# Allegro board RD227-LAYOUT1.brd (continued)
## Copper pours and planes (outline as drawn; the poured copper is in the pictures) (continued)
SHLD_SNS on TOP: 72.97,0.99 72.95,0.99 72.94,1 72.16,1.78 72.15,1.8 72.14,1.82 72.14,5.73 72.15,5.75 72.16,5.76 72.53,6.14 72.54,6.15 72.56,6.15 74.2,6.15 74.2,6.45 73.51,6.45 73.41,6.49 73.36,6.6 73.36,7.61 73.41,7.72 73.51,7.76 77.51,7.76 79.15,9.4 79.15,11.55 79.16,11.59 79.2,11.6 81.1,11.6 81.1,12.4 79.2,12.4 79.16,12.41 79.15,12.45 79.15,13.55 79.16,13.59 79.2,13.6 81.15,13.6 81.15,14.4 79.2,14.4 79.16,14.41 79.15,14.45 79.15,15.6 79.16,15.64 79.2,15.65 84.35,15.65 85.29,16.59 85.29,28.04 82.9,30.43 80.88,30.43 80.77,30.47 80.73,30.58 80.73,32.57 80.77,32.68 80.88,32.72 88.78,32.72 88.88,32.68 88.93,32.57 88.93,27.29 88.92,27.24 88.9,27.19 88.9,25.78 88.85,25.68 86.89,23.72 86.89,17.26 88.91,15.24 88.92,15.22 88.93,15.2 88.93,7.65 88.88,7.54 88.78,7.5 85.45,7.5 78.95,1 78.94,0.99 78.92,0.99
SHLD_SNS on CONDUCTIVE2: 72.21,1.74 72.2,1.75 72.2,1.77 72.2,2.72 72.19,2.75 72.19,4.67 72.2,4.7 72.2,5.78 72.2,5.8 72.21,5.81 74.14,7.74 74.15,7.75 74.17,7.75 77.45,7.75 83.42,13.72 83.44,13.74 83.46,13.74 86.55,13.74 86.58,13.72 86.6,13.69 86.6,8.67 86.59,8.65 86.58,8.63 78.95,1 78.94,0.99 78.92,0.99 73.03,0.99 72.92,1.03
SHLD_SNS on CONDUCTIVE3: 72.21,1.54 72.2,1.55 72.2,1.57 72.2,5.78 72.2,5.8 72.21,5.81 74.24,7.84 74.25,7.85 74.27,7.85 77.55,7.85 83.64,13.94 83.66,13.95 83.67,13.95 86.64,13.95 86.68,13.94 86.69,13.9 86.69,8.76 86.69,8.74 86.68,8.73 78.95,1 78.94,0.99 78.92,0.99 72.83,0.99 72.72,1.03
SIG341 on TOP: 45.7,11.8 45.66,11.81 45.65,11.85 45.65,12.03 45.65,12.05 45.66,12.06 46.6,13 46.6,13.3 46.61,13.34 46.63,13.37 46.83,13.57 46.86,13.59 46.9,13.6 47,13.6 47.1,13.5 47,13.4 46.94,13.4 46.8,13.26 46.8,12.7 46.8,12.65 46.8,12.45 46.8,12.43 46.79,12.41 46.19,11.81 46.17,11.8 46.15,11.8 45.94,11.8 45.92,11.78 45.84,11.75 45.76,11.8
SIG344 on TOP: 54.05,9.7 53.98,9.73 53.95,9.8 53.95,9.95 53.73,10.17 53.71,10.2 53.7,10.24 53.7,10.68 53.7,10.71 53.72,10.74 53.46,11 53.09,11 53.05,11.01 53.02,11.03 51.63,12.42 51.61,12.45 51.6,12.49 51.6,13.05 51.7,13.15 51.8,13.05 51.8,12.55 53.15,11.2 53.5,11.2 53.57,11.17 53.99,10.75 54.05,10.75 54.12,10.72 54.15,10.65 54.15,10.3 54.52,9.93 54.54,9.9 54.55,9.86 54.55,9.8 54.52,9.73 54.45,9.7
SIG345 on TOP: 52.9,9.65 52.83,9.68 52.8,9.75 52.8,10.01 52.81,10.05 52.83,10.08 52.85,10.1 52.85,10.6 51.13,12.32 51.11,12.35 51.1,12.39 51.1,13.05 51.2,13.15 51.3,13.05 51.3,12.45 52.98,10.77 53.19,10.77 53.26,10.74 53.29,10.67 53.29,10.11 53.47,9.93 53.49,9.9 53.5,9.86 53.5,9.75 53.47,9.68 53.4,9.65
SIG347 on TOP: 51.7,9.9 51.63,9.93 51.6,10 51.6,11.1 50.63,12.07 50.6,12.14 50.6,13.05 50.7,13.15 50.8,13.05 50.8,12.35 52.37,10.78 52.39,10.75 52.4,10.71 52.4,10 52.37,9.93 52.3,9.9
SIG369 on TOP: 46.41,10.25 46.34,10.28 46.31,10.35 46.31,11.48 46.32,11.52 46.34,11.55 47.6,12.81 47.6,13.05 47.7,13.15 47.8,13.05 47.8,12.59 47.79,12.55 47.77,12.52 47.48,12.23 47.45,12.21 47.41,12.2 47.27,12.2 46.64,11.56 46.64,10.81 46.82,10.63 46.84,10.6 46.85,10.56 46.85,10.35 46.82,10.28 46.75,10.25
SIG422 on BOTTOM: 29,11 28.96,11.01 28.95,11.05 28.95,13.2 28.96,13.24 29,13.25 29.78,13.25 29.8,13.25 29.81,13.24 30.9,12.15 31.25,12.15 31.9,12.8 31.9,14.6 31.91,14.64 31.95,14.65 32.3,14.65 32.34,14.64 32.35,14.6 32.35,12.55 32.74,12.16 32.75,12.15 32.75,12.13 32.75,11.2 32.74,11.16 32.7,11.15 30.9,11.15 30.76,11.01 30.75,11 30.73,11
SIG426 on BOTTOM: 28.65,22.35 28.61,22.36 28.6,22.4 28.6,24 28.3,24.3 26.8,24.3 26.76,24.31 26.75,24.35 26.75,26.55 26.76,26.59 26.8,26.6 29.3,26.6 29.34,26.59 29.35,26.55 29.35,23.1 29.55,22.9 29.9,22.9 29.94,22.89 29.95,22.85 29.95,22.4 29.94,22.36 29.9,22.35
SIG428 on TOP: 13.35,3.45 13.31,3.46 13.3,3.5 13.3,4.55 13.31,4.59 13.35,4.6 14.05,4.6 14.09,4.59 14.1,4.55 14.1,3.5 14.09,3.46 14.05,3.45
SIG429 on TOP: 12.25,3.85 12.21,3.86 12.2,3.9 12.2,5.2 12.21,5.24 12.25,5.25 12.65,5.25 12.69,5.24 12.7,5.2 12.7,3.9 12.69,3.86 12.65,3.85
SIG449 on BOTTOM: 28.65,20.45 28.61,20.46 28.6,20.5 28.6,21 28.61,21.04 28.65,21.05 29.15,21.05 30.04,21.94 30.05,21.95 30.07,21.95 30.35,21.95 30.65,22.25 30.65,22.85 30.66,22.89 30.7,22.9 31.95,22.9 31.99,22.89 32,22.85 32,22.47 32,22.45 31.99,22.44 31.91,22.36 31.9,22.35 31.88,22.35 31.45,22.35 30.56,21.46 30.55,21.45 30.53,21.45 30.2,21.45 29.9,21.15 29.9,20.5 29.89,20.46 29.85,20.45
SIG450 on BOTTOM: 28.27,19.1 28.25,19.1 28.24,19.11 27.21,20.14 27.2,20.15 27.2,20.17 27.2,23.5 27.05,23.65 26.8,23.65 26.76,23.66 26.75,23.7 26.75,23.95 26.76,23.99 26.8,24 27.55,24 27.59,23.99 27.6,23.95 27.6,20.4 28.45,19.55 31.6,19.55 31.61,19.56 31.75,19.7 31.75,20.2 31.45,20.5 30.65,20.5 30.61,20.51 30.6,20.55 30.6,20.95 30.61,20.99 30.65,21 31.9,21 31.94,20.99 31.95,20.95 31.95,20.7 32.39,20.26 32.4,20.25 32.4,20.23 32.4,19.3 32.39,19.26 32.35,19.25 32.35,19.15 32.34,19.11 32.3,19.1

Small or netless copper shapes (teardrops, artwork), in the pictures only: 41 on TOP, 46 on BOTTOM, 5 on CONDUCTIVE2, 14 on CONDUCTIVE3

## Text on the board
Ref Des/Silkscreen Bottom: UL
Ref Des/Silkscreen Top: 1 | 5 | 10 | 2
SYMBOL-1-BOTTOM: UL
SYMBOL-1-TOP: 1 | 5 | 10 | 2
User.5: Q101 | C121 | C122 | R110 | R117 | Q102 | D101 | IC101 | C118 | C144 | D104 | R103 | TP117 | TP118 | TP124 | TP123 | TP122 | R107 | R101 | D103 | R102 | R113 | R134 | R135 | D106 | C119 | C139 | R139 | R136 | R138 | R140 | C153 | R141 | R137 | C154 | C155 | C150 | C149 | D108 | D109 | TP103 | TP134 | TP104 | TP105 | TP133 | TP132 | TP110 | TP108 | TP111 | CURRENT COMP | VOLTAGE COMP | ADDR SELECT | TP112 | TP131 | R125 | R122 | R121 | R128 | R127 | FL101 | R124 | TP102 | R123 | C141 | D102 | D105 | R115 | D107 | R116 | R114 | TP119 | C151 | R133 | C152 | TP107 | TP106 | TP109 | UL
User.6: C106 | C102 | L101 | TP101 | C116 | CN102 | C103 | R104 | Q103 | C114 | C109 | C104 | TP125 | TP127 | TP126 | IC102 | R126 | Q106 | R112 | C133 | C131 | C143 | R130 | C123 | R131 | R132 | TP116 | C129 | R120 | C135 | R119 | C138 | R106 | C126 | TP115 | C111 | C110 | C105 | C101 | CN101 | C107 | C112 | C115 | C108 | C113 | R108 | R109 | C117 | C120 | Q104 | C145 | R111 | C142 | Q105 | C146 | TP121 | C140 | TP120 | L102 | R129 | C147 | R105 | C148 | C128 | C125 | C132 | C130 | C127 | C124 | TP114 | L103 | C134 | Q107 | TP113 | C136 | CN103 | C137 | INPUT | 1 | 2 | 5 | CONTROL | 10 | TYPE1 | OUTPUT | BUCK-BOOST
